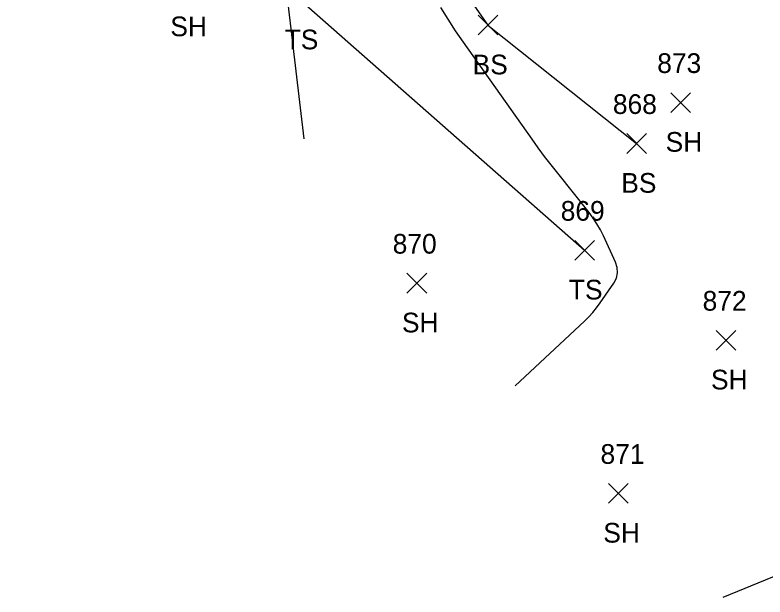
# Model space of a CAD drawing. Extents: x 1592612 to 1596497, y 111838 to 113741.
# Drawn here: x 1592734.2 to 1592810.3, y 113386.1 to 113445.2 of the extents above; entities that cross this region are included whole.
import ezdxf

# ---------------------------------------------------------------- set-up
doc = ezdxf.new("R2010")
doc.units = 0
for name, color, linetype in [('L_A', 7, 'Continuous'), ('L_I', 7, 'Continuous'), ('L_TIC', 7, 'Continuous'), ('LELB', 7, 'Continuous'), ('LSOGCMI', 7, 'Continuous')]:
    doc.layers.add(name, color=color, linetype=linetype)

msp = doc.modelspace()

# ---------------------------------------------------------------- linework, layer by layer
at = {"layer": 'L_TIC'}
for points in [[(1592781.179, 113443.146), (1592783.179, 113445.146)], [(1592783.179, 113443.146), (1592781.179, 113445.146)], [(1592800.718, 113435.287), (1592802.718, 113437.287)], [(1592802.718, 113435.287), (1592800.718, 113437.287)], [(1592796.263, 113431.126), (1592798.263, 113433.126)], [(1592798.263, 113431.126), (1592796.263, 113433.126)], [(1592790.977, 113420.287), (1592792.977, 113422.287)], [(1592792.977, 113420.287), (1592790.977, 113422.287)], [(1592773.959, 113416.944), (1592775.959, 113418.944)], [(1592775.959, 113416.944), (1592773.959, 113418.944)], [(1592805.32, 113411.152), (1592807.32, 113413.152)], [(1592807.32, 113411.152), (1592805.32, 113413.152)], [(1592794.393, 113395.598), (1592796.393, 113397.598)], [(1592796.393, 113395.598), (1592794.393, 113397.598)]]:
    msp.add_lwpolyline(points, dxfattribs=at)
at = {"layer": 'LELB'}
for points in [[(1592734.185, 113514.556), (1592751.512, 113498.984), (1592760.463, 113476.916), (1592760.688, 113460.57), (1592763.141, 113446.688), (1592791.977, 113421.287)], [(1592754.03, 113514.829), (1592761.95, 113505.931), (1592768.508, 113474.511), (1592771.317, 113463.147), (1592774.096, 113455.731), (1592782.179, 113444.146), (1592797.263, 113432.126)]]:
    msp.add_lwpolyline(points, dxfattribs=at)
at = {"layer": 'LSOGCMI'}
for points in [[(1592761.87, 113446.356), (1592763.5, 113432.609)], [(1592784.932, 113407.526), (1592791.962, 113414.087), (1592792.397, 113414.516), (1592792.807, 113414.966), (1592793.191, 113415.439), (1592793.55, 113415.933), (1592794.934, 113417.953), (1592795.205, 113418.465), (1592795.325, 113418.989), (1592795.296, 113419.526), (1592795.116, 113420.076), (1592793.888, 113422.754), (1592793.58, 113423.375), (1592793.237, 113423.973), (1592792.857, 113424.55), (1592792.442, 113425.104), (1592789.253, 113429.102), (1592788.584, 113429.953), (1592787.926, 113430.815), (1592787.281, 113431.685), (1592786.649, 113432.565), (1592779.684, 113442.402), (1592778.889, 113443.56), (1592778.131, 113444.741), (1592777.409, 113445.944)], [(1592806.043, 113386.075), (1592815.376, 113389.876)]]:
    msp.add_lwpolyline(points, dxfattribs=at)

# ---------------------------------------------------------------- texts
at = {"layer": 'L_A'}
for s, p in [('SH', (1592749.947, 113443.018)), ('TS', (1592761.55, 113441.688)), ('BS', (1592780.62, 113439.146)), ('SH', (1592800.206, 113431.287)), ('BS', (1592795.704, 113427.126)), ('TS', (1592790.387, 113416.287)), ('SH', (1592773.448, 113412.944)), ('SH', (1592804.808, 113407.152)), ('SH', (1592793.881, 113391.598))]:
    msp.add_text(s, height=2, dxfattribs=at).set_placement(p)
at = {"layer": 'L_I'}
for s, p in [('873', (1592799.355, 113439.287)), ('868', (1592794.854, 113435.126)), ('869', (1592789.56, 113424.287)), ('870', (1592772.511, 113420.944)), ('872', (1592803.958, 113415.152)), ('871', (1592793.598, 113399.598))]:
    msp.add_text(s, height=2, dxfattribs=at).set_placement(p)

doc.saveas('drawing.dxf')
